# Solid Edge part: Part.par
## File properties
Author: CADCIM
Template: normal.par
Last saved by: TIET
Revision: 16
Application: Solid Edge
Accuracy: 0.99
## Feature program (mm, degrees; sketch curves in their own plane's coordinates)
sketch for "unnamed Protrusion 1" plane through (0, 0, 0) normal (0, 0, 1) x-axis (1, 0, 0)
  line (-63.0032, 49) -> (-56, -71)
  line (-56, -71) -> (56, -71)
  line (56, -71) -> (63.0032, 49)
  line (63.0032, 49) -> (0, 54)
  line (0, 54) -> (-63.0032, 49)
  dimension (linear) = 56
  dimension (linear) = 56
extrude "unnamed Protrusion 1" add finite 4 along +normal
fillet "Round_1" radius 15
sketch for "ExtrudedProtrusion_3" plane through (0, -8.5, 0) normal (0, 0, -1) x-axis (-1, 0, 0)
extrude "ExtrudedProtrusion_3" add finite 12 along -normal
pattern "unnamed Pattern 1" of "ExtrudedProtrusion_3"
pattern "unnamed Pattern 2"
sketch for "unnamed Protrusion 2" plane through (-1.0316, 2.3101, 4) normal (0, 0, 1) x-axis (-1, 0, 0)
extrude "unnamed Protrusion 2" add finite 5 along +normal
sketch for "Hole_22" plane through (40.9331, -54.9887, 12) normal (0, 0, 1) x-axis (1, 0, 0)
  hole centre (-0.4331, -0.0113) bore radius 4.5
hole "Hole_22" diameter 9 through  CounterBoreDepth = 5 mm
pattern "unnamed Pattern 3" of "Hole_22"
hole "unnamed Hole 1" through
hole "unnamed Hole 2" through
hole "unnamed Hole 3" through
sketch for "Hole_29" plane through (-1.0316, -6.1899, 9) normal (0, 0, 1) x-axis (1, 0, 0)
  hole centre (0, 0) bore radius 11
hole "Hole_29" diameter 22 through
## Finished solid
Body 1: solid body, 34 faces, 55 edges, 18 vertices.
  Faces by surface: cylinder 18, plane 16
  Edges by curve: circle 36, line 19
Bounding box of the edges (mm): 124.346 x 125.000 x 12.000, from (-62.1729, -71, 0) to (62.1729, 54, 12).
Cylindrical faces by radius (mm): R4.5 x4, R7.5 x4, R10.7006 x4, R11 x1, R15 x4, R20 x1
Planar faces by outward normal: +z 10, -y 1, -z 1, oblique 4
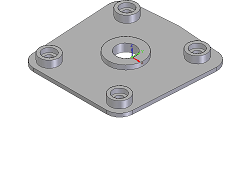
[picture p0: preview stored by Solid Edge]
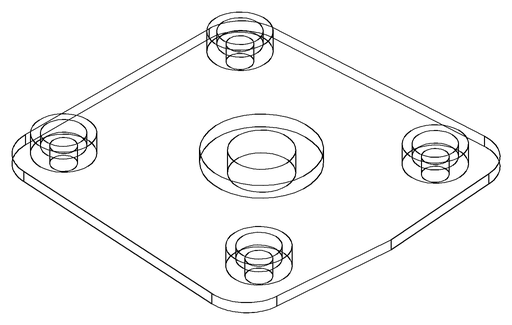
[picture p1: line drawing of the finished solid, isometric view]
